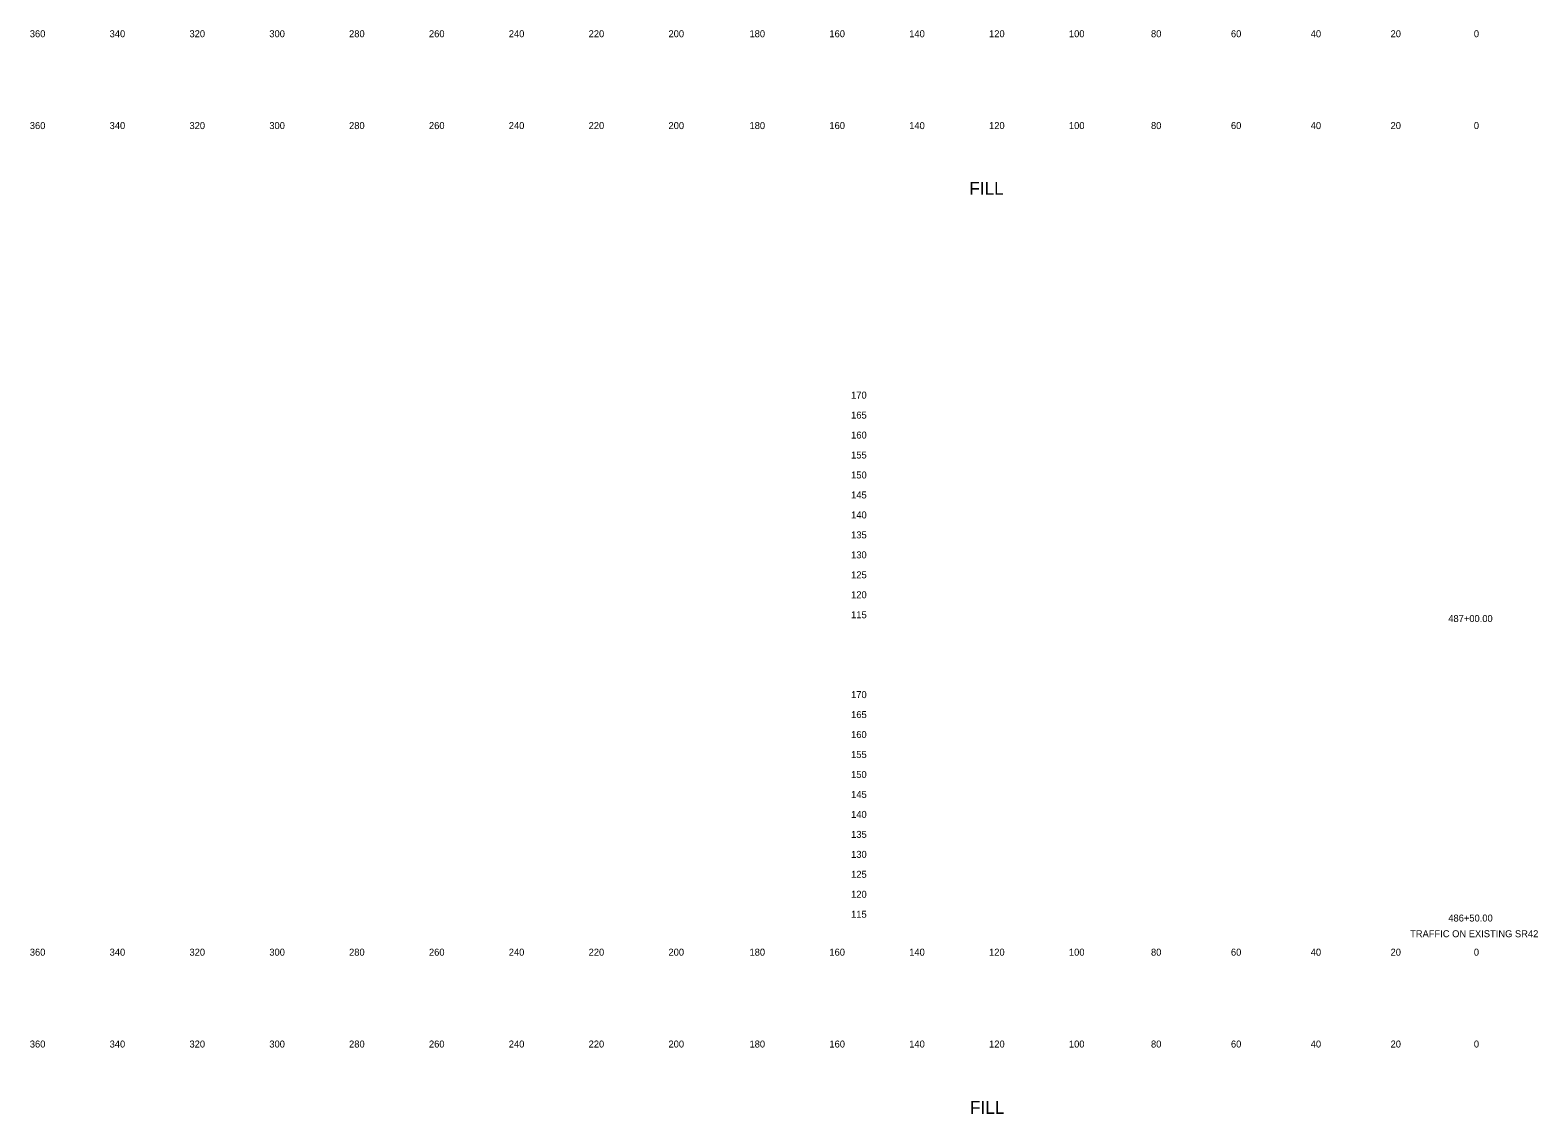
# Model space of a CAD drawing. Extents: x 21281 to 22024, y 6472 to 15198.
# Drawn here: x 21280.5 to 21658.1, y 13565.7 to 13837.1 of the extents above; entities that cross this region are included whole.
import ezdxf

# ---------------------------------------------------------------- set-up
doc = ezdxf.new("R2010")
doc.units = 0
for name, color, linetype in [('XS_SHEET_LABELS_ELEVATION', 7, 'Continuous'), ('XS_SHEET_LABELS_OFFSET', 7, 'Continuous'), ('XS_SHEET_LABELS_STATION', 7, 'Continuous')]:
    doc.layers.add(name, color=color, linetype=linetype)

msp = doc.modelspace()

# ---------------------------------------------------------------- texts
at = {"layer": 'XS_SHEET_LABELS_ELEVATION'}
for s, p in [('  170  ', (21484.84, 13744.84)), ('  165  ', (21484.84, 13739.84)), ('  160  ', (21484.84, 13734.84)), ('  155  ', (21484.84, 13729.84)), ('  150  ', (21484.84, 13724.84)), ('  145  ', (21484.84, 13719.84)), ('  140  ', (21484.84, 13714.84)), ('  135  ', (21484.84, 13709.84)), ('  130  ', (21484.84, 13704.84)), ('  125  ', (21484.84, 13699.84)), ('  120  ', (21484.84, 13694.84)), ('  115  ', (21484.84, 13689.84)), ('  170  ', (21484.84, 13669.84)), ('  165  ', (21484.84, 13664.84)), ('  160  ', (21484.84, 13659.84)), ('  155  ', (21484.84, 13654.84)), ('  150  ', (21484.84, 13649.84)), ('  145  ', (21484.84, 13644.84)), ('  140  ', (21484.84, 13639.84)), ('  135  ', (21484.84, 13634.84)), ('  130  ', (21484.84, 13629.84)), ('  125  ', (21484.84, 13624.84)), ('  120  ', (21484.84, 13619.84)), ('  115  ', (21484.84, 13614.84))]:
    msp.add_text(s, height=1.75, dxfattribs=at).set_placement(p)
at = {"layer": 'XS_SHEET_LABELS_OFFSET'}
for s, height, p in [('  360  ', 1.75, (21279.14, 13835.34)), ('  340  ', 1.75, (21299.13, 13835.34)), ('  320  ', 1.75, (21319.13, 13835.34)), ('  300  ', 1.75, (21339.13, 13835.34)), ('  280  ', 1.75, (21359.1, 13835.34)), ('  260  ', 1.75, (21379.11, 13835.34)), ('  240  ', 1.75, (21399.1, 13835.34)), ('  220  ', 1.75, (21419.1, 13835.34)), ('  200  ', 1.75, (21439.1, 13835.34)), ('  180  ', 1.75, (21459.39, 13835.34)), ('  160  ', 1.75, (21479.4, 13835.34)), ('  140  ', 1.75, (21499.39, 13835.34)), ('  120  ', 1.75, (21519.39, 13835.34)), ('  100  ', 1.75, (21539.39, 13835.34)), ('  80  ', 1.75, (21559.95, 13835.34)), ('  60  ', 1.75, (21579.97, 13835.34)), ('  40  ', 1.75, (21599.95, 13835.34)), ('  20  ', 1.75, (21619.95, 13835.34)), ('  0  ', 1.75, (21640.81, 13835.34)), ('  0  ', 1.75, (21640.81, 13835.34)), ('  360  ', 1.75, (21279.14, 13812.34)), ('  340  ', 1.75, (21299.13, 13812.34)), ('  320  ', 1.75, (21319.13, 13812.34)), ('  300  ', 1.75, (21339.13, 13812.34)), ('  280  ', 1.75, (21359.1, 13812.34)), ('  260  ', 1.75, (21379.11, 13812.34)), ('  240  ', 1.75, (21399.1, 13812.34)), ('  220  ', 1.75, (21419.1, 13812.34)), ('  200  ', 1.75, (21439.1, 13812.34)), ('  180  ', 1.75, (21459.39, 13812.34)), ('  160  ', 1.75, (21479.4, 13812.34)), ('  140  ', 1.75, (21499.39, 13812.34)), ('  120  ', 1.75, (21519.39, 13812.34)), ('  100  ', 1.75, (21539.39, 13812.34)), ('  80  ', 1.75, (21559.95, 13812.34)), ('  60  ', 1.75, (21579.97, 13812.34)), ('  40  ', 1.75, (21599.95, 13812.34)), ('  20  ', 1.75, (21619.95, 13812.34)), ('  0  ', 1.75, (21640.81, 13812.34)), ('  0  ', 1.75, (21640.81, 13812.34)), ('FILL', 3.222, (21515.74, 13795.9)), ('  360  ', 1.75, (21279.14, 13605.34)), ('  340  ', 1.75, (21299.13, 13605.34)), ('  320  ', 1.75, (21319.13, 13605.34)), ('  300  ', 1.75, (21339.13, 13605.34)), ('  280  ', 1.75, (21359.1, 13605.34)), ('  260  ', 1.75, (21379.11, 13605.34)), ('  240  ', 1.75, (21399.1, 13605.34)), ('  220  ', 1.75, (21419.1, 13605.34)), ('  200  ', 1.75, (21439.1, 13605.34)), ('  180  ', 1.75, (21459.39, 13605.34)), ('  160  ', 1.75, (21479.4, 13605.34)), ('  140  ', 1.75, (21499.39, 13605.34)), ('  120  ', 1.75, (21519.39, 13605.34)), ('  100  ', 1.75, (21539.39, 13605.34)), ('  80  ', 1.75, (21559.95, 13605.34)), ('  60  ', 1.75, (21579.97, 13605.34)), ('  40  ', 1.75, (21599.95, 13605.34)), ('  20  ', 1.75, (21619.95, 13605.34)), ('  0  ', 1.75, (21640.81, 13605.34)), ('  0  ', 1.75, (21640.81, 13605.34)), ('  360  ', 1.75, (21279.14, 13582.34)), ('  340  ', 1.75, (21299.13, 13582.34)), ('  320  ', 1.75, (21319.13, 13582.34)), ('  300  ', 1.75, (21339.13, 13582.34)), ('  280  ', 1.75, (21359.1, 13582.34)), ('  260  ', 1.75, (21379.11, 13582.34)), ('  240  ', 1.75, (21399.1, 13582.34)), ('  220  ', 1.75, (21419.1, 13582.34)), ('  200  ', 1.75, (21439.1, 13582.34)), ('  180  ', 1.75, (21459.39, 13582.34)), ('  160  ', 1.75, (21479.4, 13582.34)), ('  140  ', 1.75, (21499.39, 13582.34)), ('  120  ', 1.75, (21519.39, 13582.34)), ('  100  ', 1.75, (21539.39, 13582.34)), ('  80  ', 1.75, (21559.95, 13582.34)), ('  60  ', 1.75, (21579.97, 13582.34)), ('  40  ', 1.75, (21599.95, 13582.34)), ('  20  ', 1.75, (21619.95, 13582.34)), ('  0  ', 1.75, (21640.81, 13582.34)), ('  0  ', 1.75, (21640.81, 13582.34)), ('FILL', 3.222, (21515.91, 13565.73))]:
    msp.add_text(s, height=height, dxfattribs=at).set_placement(p)
at = {"layer": 'XS_SHEET_LABELS_STATION'}
for s, p in [('  487+00.00  ', (21634.4, 13688.89)), ('  486+50.00  ', (21634.41, 13613.89)), ('TRAFFIC ON EXISTING SR42', (21626.14, 13609.96))]:
    msp.add_text(s, height=1.75, dxfattribs=at).set_placement(p)

doc.saveas('drawing.dxf')
